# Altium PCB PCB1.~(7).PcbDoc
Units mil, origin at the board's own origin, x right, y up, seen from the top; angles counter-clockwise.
Board outline 1885.16 x 1885.16 mil, 2 copper layers (Top Layer, Bottom Layer); 25 components, 8 nets, 53 pads, 5 vias.
Unrouted connection lines stored in the file: 1.
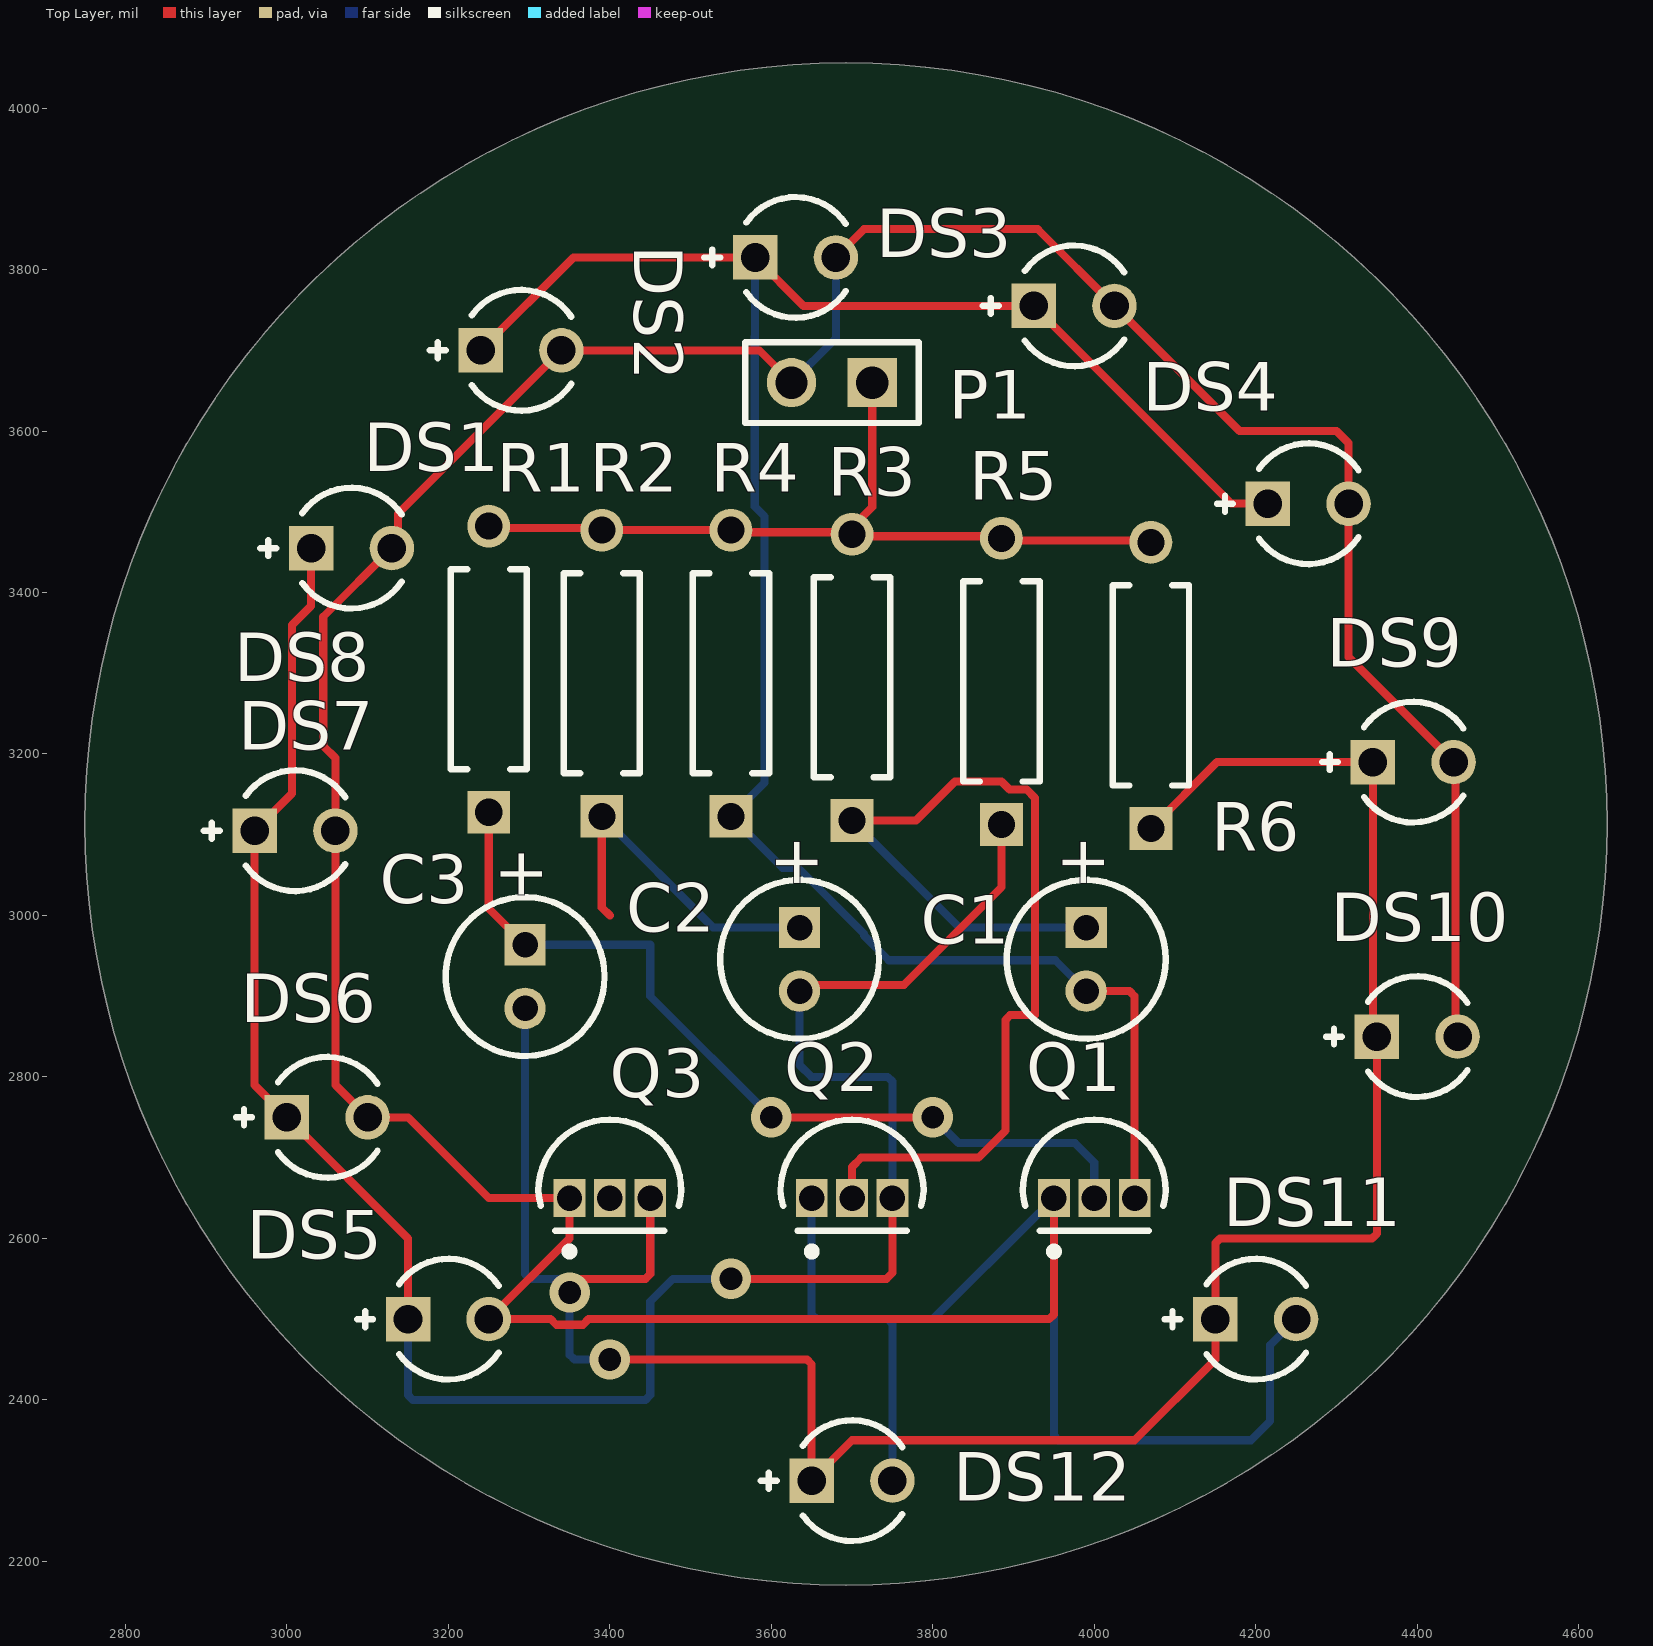
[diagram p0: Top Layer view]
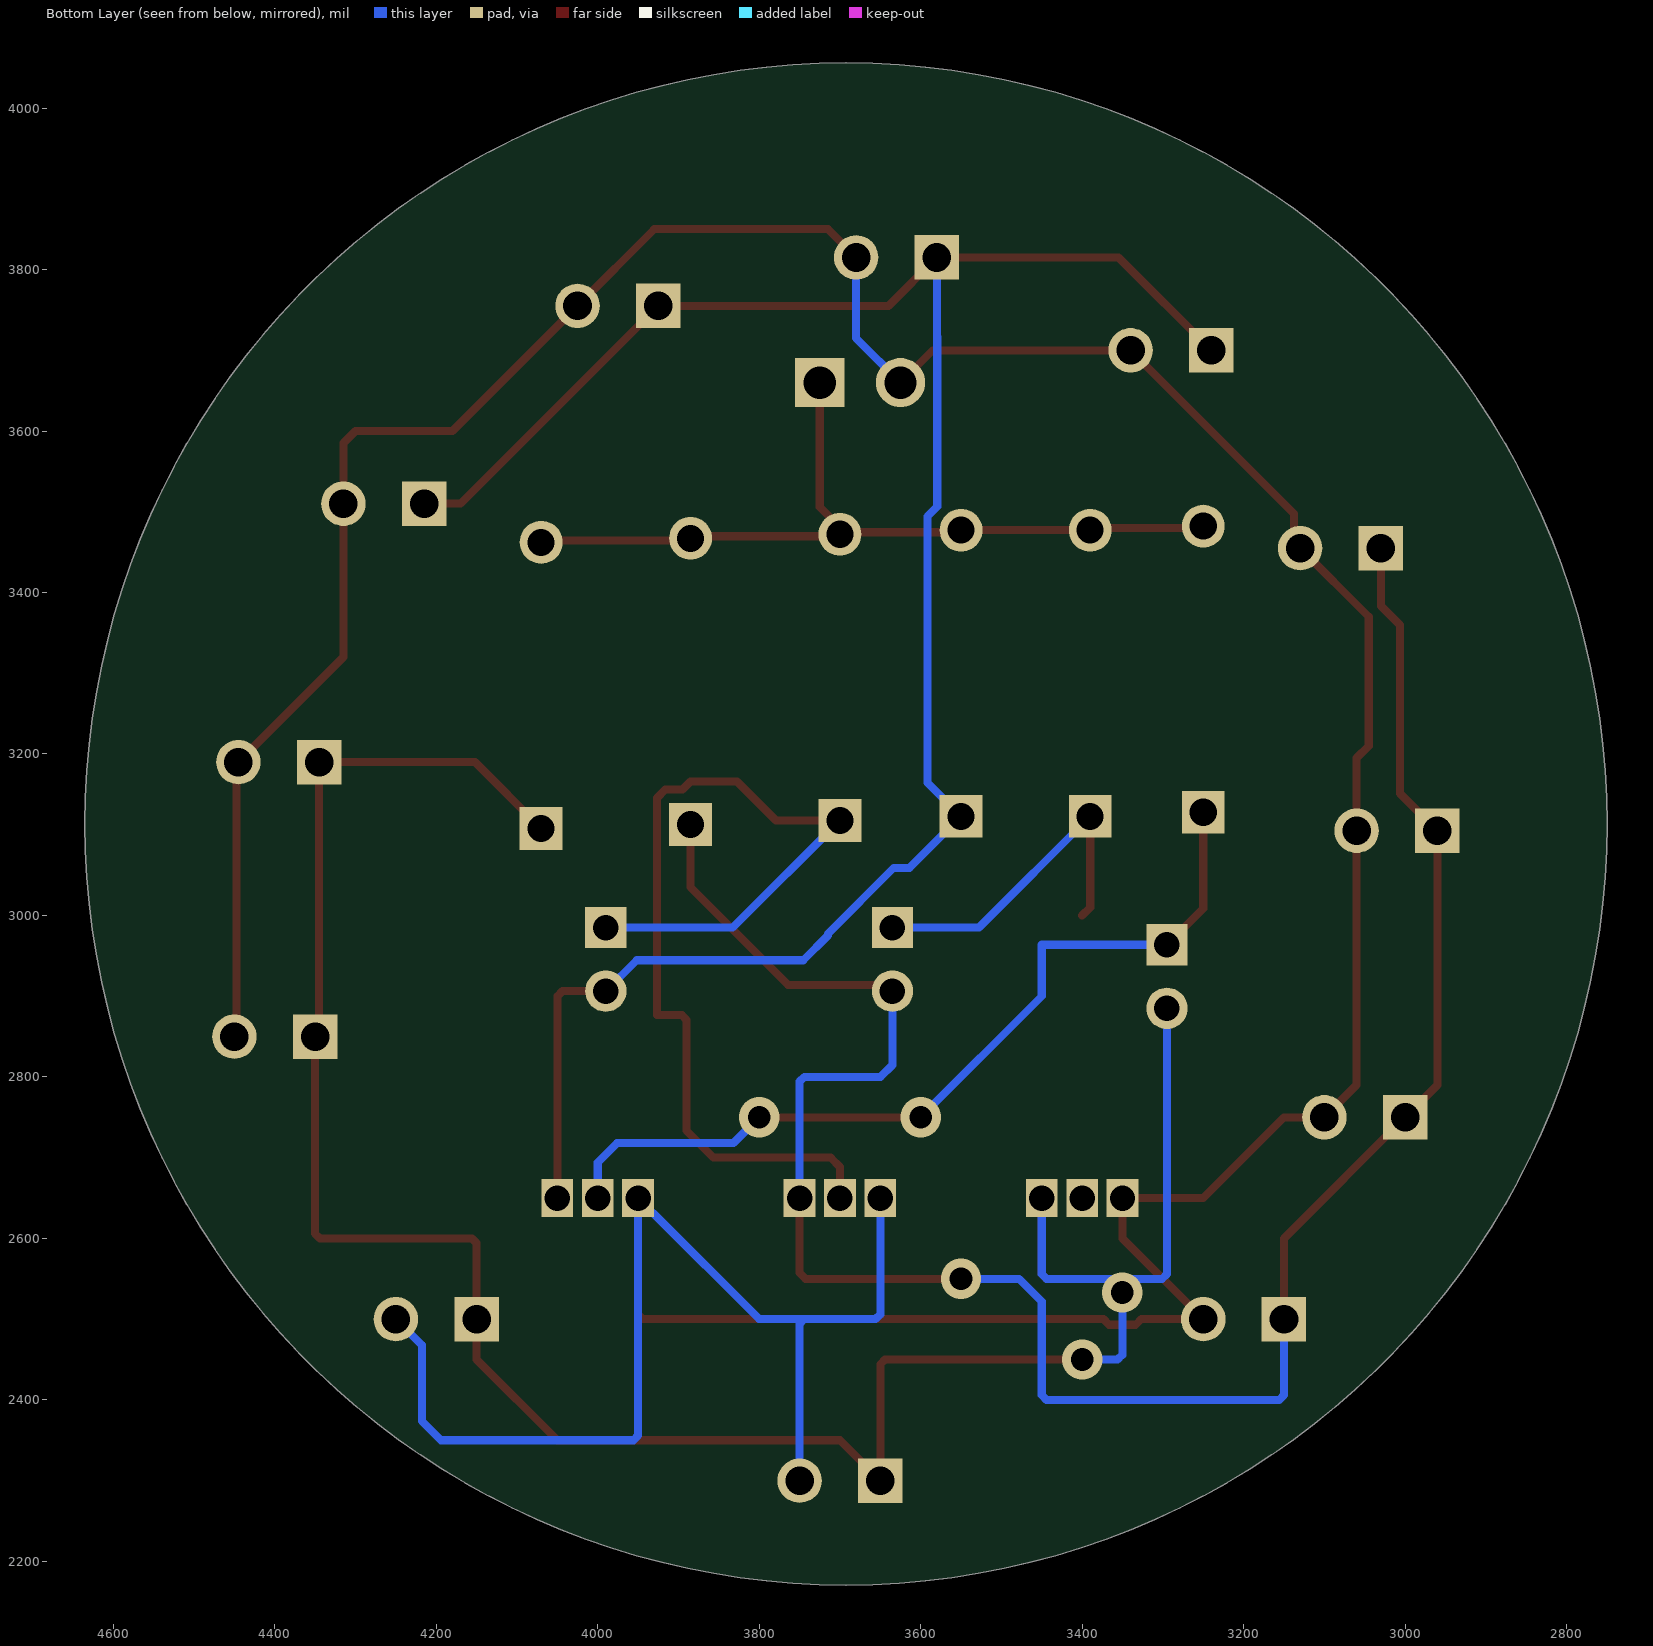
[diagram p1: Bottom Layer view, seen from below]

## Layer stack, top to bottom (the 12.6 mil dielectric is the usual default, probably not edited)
Top Solder: solder mask 0.4, Solder Resist, Dk 3.5
Top Layer: signal copper 1.4
Dielectric 1: dielectric 12.6, FR-4, Dk 4.8
Bottom Layer: signal copper 1.4
Bottom Solder: solder mask 0.4, Solder Resist, Dk 3.5

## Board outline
2749.91,3113.29 ccw(c3692.49,3113.29) 3692.49,2170.71 ccw(c3692.49,3113.29) 4635.07,3113.29 ccw(c3692.49,3113.29) 3692.49,4055.87 ccw(c3692.49,3113.29)

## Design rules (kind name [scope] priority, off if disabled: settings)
Clearance [All] p1: gap=10 ignorepadtopadclearanceinfootprint=FALSE
PolygonConnect [All] p1: connectstyle=Relief reliefconductorwidth=10 reliefentries=4 polygonreliefangle="90 Angle" airgapwidth=10
RoutingVias [All] p1: holewidth=28 width=50 viastyle="Through Hole" minholewidth=28 minwidth=50 maxholewidth=28 maxwidth=50
SolderMaskExpansion [All] p1: expansion=4 istentingtop=FALSE
Width [All] p1: maxlimit=10 minlimit=10 preferedwidth=10
30 further rules are at their usual default settings.

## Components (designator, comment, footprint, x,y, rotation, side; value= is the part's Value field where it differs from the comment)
C1 "ECA1HM220" CAPPR55-200-1100X500X1200 3990,2945.63 r270 top value=22µF
C2 "ECA1HM220" CAPPR55-200-1100X500X1200 3635,2945.63 r270 top value=22µF
C3 "ECA1HM220" CAPPR55-200-1100X500X1200 3295,2924.37 r270 top value=22µF
DS1 "LTL-1CHE" INDPR60-254-520X380X650 3290,3700 r0 top
DS2 "LTL-1CHE" INDPR60-254-520X380X650 3630,3815 r0 top
DS3 "LTL-1CHE" INDPR60-254-520X380X650 3975,3755 r0 top
DS4 "LTL-1CHE" INDPR60-254-520X380X650 4265,3510 r0 top
DS5 "LTL-1CHE" INDPR60-254-520X380X650 3200,2500 r0 top
DS6 "LTL-1CHE" INDPR60-254-520X380X650 3050,2750 r0 top
DS7 "LTL-1CHE" INDPR60-254-520X380X650 3010,3105 r0 top
DS8 "LTL-1CHE" INDPR60-254-520X380X650 3080,3455 r0 top
DS9 "LTL-1CHE" INDPR60-254-520X380X650 4395,3190 r0 top
DS10 "LTL-1CHE" INDPR60-254-520X380X650 4400,2850 r0 top
DS11 "LTL-1CHE" INDPR60-254-520X380X650 4200,2500 r0 top
DS12 "LTL-1CHE" INDPR60-254-520X380X650 3700,2300 r0 top
P1 "TSW-102-26-F-S" SMTC-TSW-102-26-XX-S 3725,3660 r180 top
Q1 "S9013" JSCJ-TO-92-3_V 4000,2650 r0 top
Q2 "S9013" JSCJ-TO-92-3_V 3700,2650 r0 top
Q3 "S9013" JSCJ-TO-92-3_V 3400,2650 r0 top
R1 "MFR-25FBF52-10K" RESA60-630X240 3250,3305 r90 top value=10k
R2 "MFR-25FBF52-10K" RESA60-630X240 3390,3300 r90 top value=10k
R3 "MFR-25FBF52-10K" RESA60-630X240 3700,3295 r90 top value=10k
R4 "MFR-25FBF52-10K" RESA60-630X240 3550,3300 r90 top value=330R
R5 "" RESA60-630X240 3885,3290 r90 top value=330R
R6 "330R" RESA60-630X240 4070,3285 r90 top

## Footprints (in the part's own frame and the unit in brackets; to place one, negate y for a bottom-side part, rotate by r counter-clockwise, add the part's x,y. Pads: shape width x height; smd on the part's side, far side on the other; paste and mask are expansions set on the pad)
CAPPR55-200-1100X500X1200 [mm] "THD, 2-Leads, Dia 5mm, Pin Spacing 2mm"
  rect 1.3x1.3 hole 0.8: 1(-1,0)
  round 1.3 hole 0.8: 2(1,0)
  silkscreen extent -2.5,-2.5 2.5,2.5, body extent -2.5,-2.5 2.45,2.5, height 12
INDPR60-254-520X380X650 [mm] "THD, 2-Leads, Dia 3.8mm, Pitch 2.54mm"
  rect 1.4x1.4 hole 0.9: 1(-1.27,0)
  round 1.4 hole 0.9: 2(1.27,0)
  silkscreen extent -2.87,-1.9 1.58,1.9, body extent -1.9,-1.9 1.9,1.9, height 6.5
JSCJ-TO-92-3_V [mm] "TO-92, 3-leads, Height 4.7mm, Pitch 1.27mm"
  rect 1x1.2 hole 0.8: 1(-1.27,0) 2(0,0) 3(1.27,0)
  silkscreen extent -2.25,-1.81 2.25,2.47, body extent -2.25,-1.03 2.25,2.47, height 4.7
RESA60-630X240 [mm] "Axial Resistor, 2-Leads, Dia 2.4mm, Body Length 6.3mm"
  rect 1.35x1.35 hole 0.85: 1(-4.5,0)
  round 1.35 hole 0.85: 2(4.5,0)
  silkscreen extent -3.15,-1.2 3.15,1.2, body extent -4.77,-1.19 4.77,1.2, height 2.4
SMTC-TSW-102-26-XX-S [mm] ".025 SQ Post Terminal Strip Assembly, 1x2 Pins, Vertical, 2.54mm Pitch, Male"
  rect 1.55x1.55 hole 1.02: 1(0,0)
  round 1.55 hole 1.02: 2(2.54,0)
  silkscreen extent -1.46,-1.27 4,1.27, body extent -1.4,-1.27 3.81,1.27, height 8.38

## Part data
C1 C2 C3: library part CMP-001-00027-7, "Aluminum Electrolytic Capacitor, 22 uF, +/- 20%, 50 V, -40 to 85 degC, 2-Pin THD, RoHS, Bulk", Capacitor Type=Electrolytic, Case/Package=Radial, Manufacturer=Panasonic, Max Operating Temperature=85°C, Min Operating Temperature=-40°C, Package Description="2-Pin Radial Lead, Dia 5 mm, Height 12 mm", Package Quantity=200, Package Reference=CAPPR55-200-1100X500X1200, Ripple Current=100mA, Tolerance=20%, Voltage Rating=50V
DS1 DS2 DS3 DS4 DS5 DS6 DS7 DS8 DS9 DS10 DS11 DS12: library part CMP-007-00018-2, "LED Uni-Color Red, 100 mW, 30 mA, -55 to 100 degC, 2-Pin THD, RoHS, Bulk", Case/Package=Radial, Colour=Red, Forward Current=20mA, Forward Voltage=2V, Manufacturer=Lite-On, Max Operating Temperature=100°C, Min Operating Temperature=-55°C, Package Description="2-Pin Through Hole Device, Dia 3.8 mm, Pitch 2.54 mm", Package Quantity=1000
P1: library part CMP-1024-00329-1, "0.025\" SQ Post Header, Through-hole, Vertical, -55 to 125 degC, 2.54 mm Pitch, 2-Pin, Male, RoHS", Manufacturer=Samtec, Temperature Range="-55 to 125 degC"
Q1 Q2 Q3: library part CMP-013-00000-3, "Transistor, NPN, 0.1 uA, 150 MHz, 3-Pin TO-92", Case/Package=TO-92-3, Manufacturer="Jiangsu Changjiang Electronics Technology", Package Description="3-Pin Through Hole Device, Height 4.7 mm, Pitch 2.3 mm"
R1 R2 R3 R4 R5 R6: library part CMP-009-00047-4, "Axial Resistor, 10 KOhm, +/- 1%, 0.25 W, -55 to 155 degC, 2-Pin THD, RoHS, Bulk", Case/Package=Axial, Manufacturer=Yageo, Max Operating Temperature=155°C, Min Operating Temperature=-55°C, Package Description="2-Pin Axial Lead, Dia 2.4 mm, Body Length 6.3 mm", Package Quantity=200, Package Reference=MFR-25, Power=250mW, Tolerance=1%, Voltage Rating=250V

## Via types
v1: diameter 50, hole 28, Top Layer to Bottom Layer, 5 vias

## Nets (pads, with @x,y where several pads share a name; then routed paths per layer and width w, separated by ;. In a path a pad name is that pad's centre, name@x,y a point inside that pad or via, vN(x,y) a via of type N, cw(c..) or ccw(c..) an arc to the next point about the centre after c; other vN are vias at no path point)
NetC1_1: C1.1 Q2.2 R3.1 | length 1292.5
  Top Layer w10: Q2.2 3700,2688.62 3711.38,2700 3856.57,2700 3890,2733.43 3890,2870.72 3895.86,2876.57 3926.57,2876.57 3926.57,3145.62 3916.39,3155.8 3895.18,3155.8 3885,3165.98 3827.36,3165.98 3779.21,3117.83 R3.1
  Bottom Layer w10: R3.1 3832.83,2985 C1.1
NetC1_2: C1.2 DS1.1 DS2.1 DS3.1 DS4.1 Q1.3 R4.1 | length 2707.3
  Top Layer w10: DS1.1 3355,3815 DS2.1 3640,3755 DS3.1 4170,3510 DS4.1 ; C1.2 4043.74,2906.26 4050,2900 Q1.3
  Bottom Layer w10: DS2.1 3580,3717.05 3579.49,3716.54 3579.49,3506.47 3591.57,3494.39 3591.57,3164.41 R4.1 3613.8,3059.03 3633.36,3059.03 3715,2977.39 3715,2975 3745.43,2944.57 3951.69,2944.57 C1.2
NetC2_1: C2.1 Q3.2 R2.1 | length 429.1
  Top Layer w10: R2.1 3390,3010 3400,3000
  Bottom Layer w10: R2.1 3527.83,2985 C2.1
NetC2_2: C2.2 DS5.1 DS6.1 DS7.1 DS8.1 Q2.3 R5.1 | length 2725.1
  Top Layer w10: DS8.1 3030,3383.28 3006.28,3359.56 3006.28,3151.28 DS7.1 2960,2790 DS6.1 3150,2600 DS5.1 ; v1(3550,2550) 3742.49,2550 3750,2557.51 Q2.3 ; C2.2 3642.88,2914.14 3764.14,2914.14 3885,3035 R5.1
  Bottom Layer w10: DS5.1 3150,2405.86 3155.86,2400 3444.14,2400 3450,2405.86 3450,2521.72 3478.28,2550 v1(3550,2550) ; C2.2 3635,2815 3650,2800 3744.14,2800 3750,2794.14 Q2.3
NetC3_1: C3.1 Q1.2 R1.1 | length 1080.9
  Top Layer w10: R1.1 3250,3008.74 C3.1 ; v1(3600,2750) v1(3800,2750)
  Bottom Layer w10: C3.1 3450,2963.74 3450,2900 v1(3600,2750) ; v1(3800,2750) 3831.76,2718.24 3975.9,2718.24 4000,2694.14 Q1.2
NetC3_2: C3.2 DS9.1 DS10.1 DS11.1 DS12.1 Q3.3 R6.1 | length 3126.1
  Top Layer w10: v1(3350.25,2533.05) 3350,2532.8 3350,2544.14 3355.86,2550 3444.14,2550 3450,2555.86 Q3.3 ; v1(3400,2450) 3644.14,2450 3650,2444.14 DS12.1 3700,2350 4050,2350 4150,2450 DS11.1 4150,2594.14 4155.86,2600 4344.14,2600 4350,2605.86 DS10.1 4345,2855 DS9.1 4152.17,3190 R6.1
  Bottom Layer w10: C3.2 3295,2555.86 3300.86,2550 3444.14,2550 3450,2555.86 Q3.3 ; v1(3350.25,2533.05) 3350.25,2455.86 3356.11,2450 v1(3400,2450)
NetDS1_2: DS1.2 DS2.2 DS3.2 DS4.2 DS5.2 DS6.2 DS7.2 DS8.2 DS9.2 DS10.2 DS11.2 DS12.2 P1.2 Q1.1 Q2.1 Q3.1 | length 5887
  Top Layer w10: P1.2 3585,3700 DS1.2 3137.56,3497.56 3137.56,3462.56 DS8.2 3045,3370 3045,3210 3060,3195 DS7.2 3060,2790 DS6.2 3150,2750 3250,2650 Q3.1 3350,2600 DS5.2 3326.74,2500 3333.69,2493.05 3366.82,2493.05 3373.77,2500 3944.14,2500 3950,2505.86 Q1.1 ; DS2.2 3715,3850 3930,3850 DS3.2 4180,3600 4300,3600 4315,3585 DS4.2 4315,3320 DS9.2 4447.5,3187.5 4447.5,2852.5 DS10.2
  Bottom Layer w10: P1.2 3680,3715 DS2.2 ; Q2.1 3650,2505.86 3655.86,2500 3744.14,2500 ; DS12.2 3750,2494.14 3744.14,2500 ; DS11.2 4217.75,2467.75 4217.75,2373.61 4194.14,2350 3955.86,2350 3950,2355.86 Q1.1 3950,2646.06 3935.31,2631.38 3931.38,2631.38 3800,2500 3744.14,2500
NetP1_1: P1.1 R1.2 R2.2 R3.2 R4.2 R5.2 R6.2 | length 1026.5
  Top Layer w10: R1.2 3252.5,3479.67 3387.5,3479.67 R2.2 R4.2 3552.5,3474.67 3697.5,3474.67 R3.2 ; P1.1 3725,3505.96 3700,3480.96 R3.2 ; R6.2 4067.5,3464.67 3887.5,3464.67 R5.2 3882.5,3469.67 3702.5,3469.67 R3.2

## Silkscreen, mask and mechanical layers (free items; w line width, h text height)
Mechanical 1:
  circle w10: c3692.49,3113.29 r942.58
